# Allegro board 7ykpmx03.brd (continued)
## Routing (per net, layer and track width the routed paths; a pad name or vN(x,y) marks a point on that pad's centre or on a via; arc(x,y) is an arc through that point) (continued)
GND_OSC1: length 2.5
  TOP w0.254: R45.1 R47.2 X_OSC1.3
GND_SIGNAL: length 331.3
  TOP w0.254: 170.56,302.29 C127.1 ; C127.1 170.13,302.72 ; C127.1 170.99,302.72 ; 168.86,302.72 C128.1 ; C128.1 169.29,302.29 ; C128.1 169.72,302.72 ; C125.1 170.56,306.04 ; C125.1 170.13,305.61 ; C125.1 170.99,305.61 ; 171.4,302.72 R184.1 ; R184.1 172.26,302.72 ; R184.1 171.83,302.29 ; C126.1 169.29,306.04 ; C126.1 168.86,305.61 ; C126.1 169.72,305.61 ; 171.4,305.61 R183.1 ; R183.1 171.83,306.04 ; R183.1 172.26,305.61
  TOP w0.381: P_OCPEDGE.A19 128.31,323.9 v1(128.11,323.7) ; P_OCPEDGE.A22 126.51,323.9 v1(126.31,323.7) ; P_OCPEDGE.A16 130.11,323.9 v1(129.91,323.7) ; v1(104.19,323.7) 104.39,323.9 P_OCPEDGE.A46 ; v1(124.51,323.7) 124.71,323.9 P_OCPEDGE.A25 ; v1(115.1,323.7) 115.3,323.9 P_OCPEDGE.A35 ; v1(131.71,323.7) 131.91,323.9 P_OCPEDGE.A13 ; P_OCPEDGE.A29 118.9,323.9 v1(118.7,323.7) ; P_OCPEDGE.A41 111.7,323.9 v1(111.5,323.7) ; P_OCPEDGE.A61 95.39,323.9 v1(95.19,323.7) ; P_OCPEDGE.A67 91.79,323.9 v1(91.59,323.7) ; P_OCPEDGE.A28 122.91,323.9 v1(122.71,323.7) ; v1(105.99,323.7) 106.19,323.9 P_OCPEDGE.A43 ; P_OCPEDGE.A38 113.5,323.9 v1(113.3,323.7) ; P_OCPEDGE.A49 102.59,323.9 v1(102.39,323.7) ; v1(93.39,323.7) 93.59,323.9 P_OCPEDGE.A64 ; P_OCPEDGE.OCP_A13 144.11,323.9 v1(143.9,323.7) ; P_OCPEDGE.A55 98.99,323.9 v1(98.79,323.7) ; P_OCPEDGE.A52 100.79,323.9 v1(100.59,323.7) ; v1(96.99,323.7) 97.19,323.9 P_OCPEDGE.A58 ; P_OCPEDGE.A32 117.1,323.9 v1(116.9,323.7) ; v1(145.7,323.7) 145.91,323.9 P_OCPEDGE.OCP_A10
  GND w0.254: P_CAL_CPU_OCP_0_P.2 178.99,299.09 ; P_CAL_CPU_OCP_0_P.2 178.99,300.21 ; P_CAL_CPU_OCP_0_P.2 177.86,300.21 ; P_CAL_CPU_OCP_0_N.5 178.99,308.12 ; P_CAL_CPU_OCP_0_N.5 177.86,308.12 ; P_CAL_CPU_OCP_0_N.5 178.99,309.24 ; 71.93,314.45 J_S2D_BOT.1 ; J_S2D_BOT.1 72.85,314.45 ; J_S2D_BOT.1 72.39,313.23 ; J_S2D_BOT.1 72.39,315.67 ; P_CAL_CPU_OCP_0_P.3 178.99,295.74 ; P_CAL_CPU_OCP_0_P.3 177.86,295.74 ; P_CAL_CPU_OCP_0_P.3 177.86,296.86 ; P_CAL_CPU_OCP_0_P.3 178.99,296.86 ; P_CAL_CPU_OCP_0_N.3 174.69,311.47 ; P_CAL_CPU_OCP_0_N.3 173.56,311.47 ; P_CAL_CPU_OCP_0_N.3 174.69,312.59 ; P_CAL_CPU_OCP_0_N.3 173.56,312.59 ; P_CAL_CPU_OCP_0_P.4 174.69,296.86 ; P_CAL_CPU_OCP_0_P.4 173.56,296.86 ; P_CAL_CPU_OCP_0_P.4 173.56,295.74 ; P_CAL_CPU_OCP_0_P.4 174.69,295.74 ; J_S2D_TOP.1 72.85,294 ; J_S2D_TOP.1 72.39,295.22 ; J_S2D_TOP.1 72.39,292.79 ; J_S2D_TOP.1 71.93,294 ; 177.86,311.47 P_CAL_CPU_OCP_0_N.4 ; P_CAL_CPU_OCP_0_N.4 178.99,312.59 ; P_CAL_CPU_OCP_0_N.4 177.86,312.59 ; P_CAL_CPU_OCP_0_N.4 178.99,311.47 ; P_CAL_CPU_OCP_0_P.5 174.69,300.21 ; P_CAL_CPU_OCP_0_P.5 173.56,300.21 ; P_CAL_CPU_OCP_0_P.5 173.56,299.09 ; P_CAL_CPU_OCP_0_N.2 174.69,308.12 ; P_CAL_CPU_OCP_0_N.2 173.56,308.12 ; P_CAL_CPU_OCP_0_N.2 173.56,309.24
  VCC w0.254: P_CAL_CPU_OCP_0_N.5 178.99,308.12 ; P_CAL_CPU_OCP_0_N.5 177.86,308.12 ; P_CAL_CPU_OCP_0_N.5 178.99,309.24 ; 173.56,300.21 P_CAL_CPU_OCP_0_P.5 ; P_CAL_CPU_OCP_0_P.5 174.69,300.21 ; P_CAL_CPU_OCP_0_P.5 173.56,299.09 ; P_CAL_CPU_OCP_0_P.2 178.99,299.09 ; P_CAL_CPU_OCP_0_P.2 177.86,300.21 ; P_CAL_CPU_OCP_0_P.2 178.99,300.21 ; 72.39,313.23 J_S2D_BOT.1 ; J_S2D_BOT.1 72.85,314.45 ; J_S2D_BOT.1 71.93,314.45 ; J_S2D_BOT.1 72.39,315.67 ; P_CAL_CPU_OCP_0_N.3 174.69,311.47 ; P_CAL_CPU_OCP_0_N.3 173.56,312.59 ; P_CAL_CPU_OCP_0_N.3 174.69,312.59 ; P_CAL_CPU_OCP_0_N.3 173.56,311.47 ; 173.56,296.86 P_CAL_CPU_OCP_0_P.4 ; P_CAL_CPU_OCP_0_P.4 173.56,295.74 ; P_CAL_CPU_OCP_0_P.4 174.69,295.74 ; P_CAL_CPU_OCP_0_P.4 174.69,296.86 ; 177.86,295.74 P_CAL_CPU_OCP_0_P.3 ; P_CAL_CPU_OCP_0_P.3 178.99,295.74 ; P_CAL_CPU_OCP_0_P.3 177.86,296.86 ; P_CAL_CPU_OCP_0_P.3 178.99,296.86 ; P_CAL_CPU_OCP_0_N.4 178.99,311.47 ; P_CAL_CPU_OCP_0_N.4 177.86,312.59 ; P_CAL_CPU_OCP_0_N.4 178.99,312.59 ; P_CAL_CPU_OCP_0_N.4 177.86,311.47 ; 173.56,308.12 P_CAL_CPU_OCP_0_N.2 ; P_CAL_CPU_OCP_0_N.2 173.56,309.24 ; P_CAL_CPU_OCP_0_N.2 174.69,308.12 ; J_S2D_TOP.1 72.39,295.22 ; J_S2D_TOP.1 71.93,294 ; J_S2D_TOP.1 72.85,294 ; J_S2D_TOP.1 72.39,292.79
  GD2 w0.254: 177.86,309.24 P_CAL_CPU_OCP_0_N.5 ; P_CAL_CPU_OCP_0_N.5 178.99,308.12 ; P_CAL_CPU_OCP_0_N.5 178.99,309.24 ; P_CAL_CPU_OCP_0_N.5 177.86,308.12 ; P_CAL_CPU_OCP_0_N.4 178.99,312.59 ; P_CAL_CPU_OCP_0_N.4 177.86,312.59 ; P_CAL_CPU_OCP_0_N.4 178.99,311.47 ; P_CAL_CPU_OCP_0_N.4 177.86,311.47 ; P_CAL_CPU_OCP_0_N.2 174.69,309.24 ; P_CAL_CPU_OCP_0_N.2 174.69,308.12 ; P_CAL_CPU_OCP_0_N.2 173.56,308.12 ; P_CAL_CPU_OCP_0_N.2 173.56,309.24 ; P_CAL_CPU_OCP_0_N.3 174.69,311.47 ; P_CAL_CPU_OCP_0_N.3 174.69,312.59 ; P_CAL_CPU_OCP_0_N.3 173.56,312.59 ; P_CAL_CPU_OCP_0_N.3 173.56,311.47 ; 173.56,300.21 P_CAL_CPU_OCP_0_P.5 ; P_CAL_CPU_OCP_0_P.5 173.56,299.09 ; P_CAL_CPU_OCP_0_P.5 174.69,299.09 ; P_CAL_CPU_OCP_0_P.5 174.69,300.21 ; J_S2D_BOT.1 72.39,315.67 ; J_S2D_BOT.1 72.85,314.45 ; J_S2D_BOT.1 72.39,313.23 ; J_S2D_BOT.1 71.93,314.45 ; 177.86,296.86 P_CAL_CPU_OCP_0_P.3 ; P_CAL_CPU_OCP_0_P.3 178.99,296.86 ; P_CAL_CPU_OCP_0_P.3 178.99,295.74 ; P_CAL_CPU_OCP_0_P.3 177.86,295.74 ; P_CAL_CPU_OCP_0_P.4 174.69,295.74 ; P_CAL_CPU_OCP_0_P.4 173.56,296.86 ; P_CAL_CPU_OCP_0_P.4 173.56,295.74 ; P_CAL_CPU_OCP_0_P.4 174.69,296.86 ; J_S2D_TOP.1 72.85,294 ; J_S2D_TOP.1 71.93,294 ; J_S2D_TOP.1 72.39,295.22 ; J_S2D_TOP.1 72.39,292.79 ; P_CAL_CPU_OCP_0_P.2 178.99,300.21 ; P_CAL_CPU_OCP_0_P.2 178.99,299.09 ; P_CAL_CPU_OCP_0_P.2 177.86,299.09 ; P_CAL_CPU_OCP_0_P.2 177.86,300.21
  GD3 w0.254: P_CAL_CPU_OCP_0_P.4 174.69,295.74 ; P_CAL_CPU_OCP_0_P.4 173.56,296.86 ; P_CAL_CPU_OCP_0_P.4 174.69,296.86 ; P_CAL_CPU_OCP_0_P.4 173.56,295.74 ; 177.86,300.21 P_CAL_CPU_OCP_0_P.2 ; P_CAL_CPU_OCP_0_P.2 177.86,299.09 ; P_CAL_CPU_OCP_0_P.2 178.99,299.09 ; P_CAL_CPU_OCP_0_P.2 178.99,300.21 ; P_CAL_CPU_OCP_0_P.5 174.69,300.21 ; P_CAL_CPU_OCP_0_P.5 174.69,299.09 ; P_CAL_CPU_OCP_0_P.5 173.56,300.21 ; P_CAL_CPU_OCP_0_P.5 173.56,299.09 ; 173.56,308.12 P_CAL_CPU_OCP_0_N.2 ; P_CAL_CPU_OCP_0_N.2 173.56,309.24 ; P_CAL_CPU_OCP_0_N.2 174.69,309.24 ; P_CAL_CPU_OCP_0_N.2 174.69,308.12 ; 177.86,312.59 P_CAL_CPU_OCP_0_N.4 ; P_CAL_CPU_OCP_0_N.4 178.99,312.59 ; P_CAL_CPU_OCP_0_N.4 177.86,311.47 ; P_CAL_CPU_OCP_0_N.4 178.99,311.47 ; P_CAL_CPU_OCP_0_N.3 174.69,312.59 ; P_CAL_CPU_OCP_0_N.3 173.56,312.59 ; P_CAL_CPU_OCP_0_N.3 173.56,311.47 ; P_CAL_CPU_OCP_0_N.3 174.69,311.47 ; P_CAL_CPU_OCP_0_N.5 178.99,308.12 ; P_CAL_CPU_OCP_0_N.5 177.86,309.24 ; P_CAL_CPU_OCP_0_N.5 177.86,308.12 ; P_CAL_CPU_OCP_0_N.5 178.99,309.24 ; J_S2D_TOP.1 72.85,294 ; J_S2D_TOP.1 71.93,294 ; J_S2D_TOP.1 72.39,292.79 ; J_S2D_TOP.1 72.39,295.22 ; P_CAL_CPU_OCP_0_P.3 178.99,295.74 ; P_CAL_CPU_OCP_0_P.3 178.99,296.86 ; P_CAL_CPU_OCP_0_P.3 177.86,296.86 ; P_CAL_CPU_OCP_0_P.3 177.86,295.74 ; 71.93,314.45 J_S2D_BOT.1 ; J_S2D_BOT.1 72.39,315.67 ; J_S2D_BOT.1 72.85,314.45 ; J_S2D_BOT.1 72.39,313.23
  BOTTOM w0.381: P_OCPEDGE.OCP_A13 144.11,323.9 v1(143.9,323.7) ; P_OCPEDGE.A58 97.19,323.9 v1(96.99,323.7) ; v1(113.3,323.7) 113.5,323.9 P_OCPEDGE.A38 ; v1(104.19,323.7) 104.39,323.9 P_OCPEDGE.A46 ; P_OCPEDGE.A22 126.51,323.9 v1(126.31,323.7) ; P_OCPEDGE.A28 122.91,323.9 v1(122.71,323.7) ; P_OCPEDGE.OCP_A6 148.31,323.9 v1(148.1,323.7) ; P_OCPEDGE.A61 95.39,323.9 v1(95.19,323.7) ; v1(118.7,323.7) 118.9,323.9 P_OCPEDGE.A29 ; P_OCPEDGE.A19 128.31,323.9 v1(128.11,323.7) ; v1(93.39,323.7) 93.59,323.9 P_OCPEDGE.A64 ; v1(115.1,323.7) 115.3,323.9 P_OCPEDGE.A35 ; v1(116.9,323.7) 117.1,323.9 P_OCPEDGE.A32 ; v1(129.91,323.7) 130.11,323.9 P_OCPEDGE.A16 ; P_OCPEDGE.A67 91.79,323.9 v1(91.59,323.7) ; P_OCPEDGE.A43 106.19,323.9 v1(105.99,323.7) ; P_OCPEDGE.A49 102.59,323.9 v1(102.39,323.7) ; v1(111.5,323.7) 111.7,323.9 P_OCPEDGE.A41 ; P_OCPEDGE.A52 100.79,323.9 v1(100.59,323.7) ; v1(131.71,323.7) 131.91,323.9 P_OCPEDGE.A13 ; P_OCPEDGE.OCP_A10 145.91,323.9 v1(145.7,323.7) ; v1(98.79,323.7) 98.99,323.9 P_OCPEDGE.A55 ; v1(124.51,323.7) 124.71,323.9 P_OCPEDGE.A25
  vias: v1(136.02,323.7) v1(136.91,323.7) v1(137.8,323.7) v1(138.68,323.7) v1(169.29,306.45) v1(169.29,301.88) v1(170.56,306.45) v1(170.56,301.88) v1(171.83,306.45) v1(171.83,301.88) v2(175.53,309.88) v2(175.53,298.45) v2(175.63,310.25) v2(175.63,309.51) v2(175.63,298.82) v2(175.63,298.08) v2(175.9,310.53) v2(175.9,297.8) v2(176.28,310.63) v2(176.28,297.7) v2(176.65,310.53) v2(176.65,297.8) v2(176.92,310.25) v2(176.92,309.51) v2(176.92,298.82) v2(176.92,298.08) v2(177.03,309.88) v2(177.03,298.45)
VCC_OSC1: length 4.2
  TOP w0.254: C23.1 111.47,251.78 ; C23.1 111.14,251.46 ; C23.1 111.8,251.46 ; 112.43,254.84 R37.1 ; R37.1 112.86,254.41 ; R37.1 113.3,254.84 ; R35.1 112.81,251.46 ; R35.1 112.48,251.78 ; R35.1 112.16,251.46 ; R36.1 110.78,251.46 ; R36.1 110.45,251.78 ; R36.1 110.12,251.46
317_ADJ: length 4.1
  TOP w0.102: 116.55,256.83 116.55,258.27 R94.2 115.58,258.78 115.44,258.91 115.44,259.46 115.27,259.64 R96.1
337_ADJ: length 3.4
  TOP w0.102: R100.2 R99.1 163.83,238.38 163.82,238.37 U10.1
555_DISCHARGE: length 0.9
  TOP w0.254: 13.77,219.63 R24.1 14.2,219.2
555_OUT: length 3.1
  TOP w0.102: 22.74,220.34 22.74,220.72 22.56,220.9 R27.1 22.1,221.23 21.72,220.85 20.61,220.85
555_OUT_JP: length 11.4
  TOP w0.102: R27.2 v1(24.26,221.23)
  BOTTOM w0.102: v1(24.26,221.23) 24.64,221.62 27.56,221.62 28.32,220.85 32.51,220.85 P3.1
555_RST_N: length 3.6
  TOP w0.102: C11.1 22.28,223.22 22.56,222.94 R26.2 22.1,222.38 21.84,222.12 20.61,222.12
555_TRI: length 26
  TOP w0.102: R19.2 17.02,238.76 16.26,238 16.26,225.55 18.8,223.01 18.8,220.09 19.3,219.58 22.74,219.58
ATX_PS_ON_N: length 78
  TOP w0.102: SW_PWR.5 212.34,253.11 212.34,250.32 211.51,249.48 DS2.4
  BOTTOM w0.102: P_ATX.16 161.67,252.61 175.39,252.61 178.56,255.78 178.56,257.3 179.2,257.94 181.23,257.94 182.25,256.92 182.25,249.43 183.64,248.03 207.52,248.03 210.44,250.95 210.44,253.17 SW_PWR.5
ATX_PWR_OK: length 170.4
  TOP w0.102: R102.2 22.56,245.19 v1(22.48,245.11)
  BOTTOM w0.102: P_ATX.8 168.05,264.54 73.79,264.54 63.25,254 28.58,254 24.64,250.06 22.23,250.06 21.84,249.68 21.84,248.41 22.48,247.78 v1(22.48,245.11)
ATX_PWR_OK_33: length 3
  TOP w0.102: R102.1 R103.2 24.13,247.65 24.2,247.72 U11.3
AUX_PWR_EN: length 280.5
  TOP w0.102: v1(91.82,88.39) 91.86,88.35 P_OCP.B12 ; v1(21.59,245.11) 21.21,245.49 21.21,248.03 21.72,248.54 26.92,248.54 27.21,248.25 U11.2 28.01,247.72 28.07,247.78 R104.2 28.78,249.61 28.27,250.12 U12.3
  BOTTOM w0.102: v1(91.82,88.39) 91.82,85.34 92.33,84.84 92.33,84.07 90.96,82.7 87.1,82.7 86.61,83.19 82.64,83.19 74.39,74.93 47.5,74.93 45.09,77.34 35.05,77.34 27.81,84.58 27.81,106.3 49.15,127.64 49.15,199.64 33.08,215.71 27.11,215.71 22.99,219.84 22.99,224.03 19.3,227.71 19.3,242.32 21.59,244.6 v1(21.59,245.11)
BIF0_N: length 70.4
  TOP w0.102: R14.2 38.35,88.9 38.53,88.72 R12.2 38.53,87.3 38.28,87.05 37.13,87.05 36.83,86.74 36.83,84.2 35.81,83.19 35.81,81.66 v1(36.2,81.28) ; v1(85.72,85.09) 86.11,85.47 88.52,85.47 88.86,85.81 P_OCP.B7
  BOTTOM w0.102: v1(36.2,81.28) 36.2,80.9 35.56,80.26 35.56,79.25 36.07,78.74 47.37,78.74 48.77,77.34 68.96,77.34 70.61,78.99 77.48,78.99 83.58,85.09 v1(85.72,85.09)
BIF1_N: length 70.6
  TOP w0.102: R6.2 36.32,88.78 36.5,88.6 R13.2 36.5,87.17 36.2,86.87 36.2,84.46 35.18,83.45 v1(35.18,81.28) ; v1(87,84.71) 87.5,85.22 89.03,85.22 89.46,85.65 P_OCP.B8
  BOTTOM w0.102: v1(87,84.71) 86.11,84.71 85.98,84.58 83.39,84.58 77.42,78.61 71.25,78.61 69.22,76.58 47.88,76.58 46.1,78.36 35.91,78.36 35.18,79.09 v1(35.18,81.28)
BIF2_N: length 73.3
  TOP w0.102: R7.2 34.29,88.78 34.47,88.6 R5.2 34.47,87.71 35.56,86.61 35.56,84.73 34.54,83.71 34.54,81.66 v1(34.16,81.28) ; v1(88.01,84.71) 88.9,84.71 90.06,85.87 P_OCP.B9
  BOTTOM w0.102: v1(34.16,81.28) 34.16,80.9 34.8,80.26 34.8,78.93 35.75,77.98 44.96,77.98 47.62,75.31 74.45,75.31 83.34,84.2 87.25,84.2 87.76,84.71 v1(88.01,84.71)
BTN_NC: length 16.9
  TOP w0.102: U1.1 21.03,236.24 20.83,236.44 v1(20.83,236.86) ; SW1.1 20.45,228.73 21.21,227.97 v1(21.21,227.46) 21.46,227.21 R31.1 R20.1
  BOTTOM w0.102: v1(21.21,227.46) 19.94,228.73 19.94,235.97 v1(20.83,236.86)
BTN_NO: length 36.3
  TOP w0.102: U6.2 21.21,229.24 20.7,229.74 20.7,231.14 21.59,232.03 21.59,232.79 20.83,233.55 19.5,233.55 19.14,233.91 SW1.3 19.14,238.21 19.3,238.38 19.3,238.76 R19.1 19.3,239.15 19.18,239.27 18.69,239.27 18.62,239.34 R28.1 v1(18.62,240.74) ; DS1.4 v1(20.7,259.64)
  BOTTOM w0.102: v1(18.62,240.74) 18.62,257.56 v1(20.7,259.64)
BUS_SEL: length 230
  TOP w0.102: R30.1 24.77,220.98 24.13,220.34 R29.1 ; R30.1 25.35,221.54 25.2,221.69 C15.1 ; R30.1 25.35,220.78 26.54,219.58 P4.1 30.73,220.98 30.73,222.5 27.81,225.43 21.34,225.43 20.96,225.8 R31.2 ; U8.10 105.56,240.01 105.28,239.74 105.28,239.4 v1(104.77,238.89) ; Q2.1 189.61,229.55 v1(189.61,229.56) ; v1(52.7,217.17) v1(29.84,217.17)
  BOTTOM w0.102: v1(189.61,229.56) 188.02,227.97 152.27,227.97 141.35,238.89 v1(104.77,238.89) 106.05,237.62 106.05,231.39 104.9,230.25 81.91,230.25 78.99,227.33 78.99,216.28 80.01,215.27 80.01,210.06 79.12,209.17 65.02,209.17 64.01,210.19 56.9,210.19 55.24,211.84 55.24,214.63 v1(52.7,217.17) ; v1(29.84,217.17) 29.84,219.08 P4.1
CLK_BASE_TO_DEVICE_DN: length 103.1
  TOP w0.127: R111.1 62.51,206.76 ; 62.51,206.76 62.38,206.63 62.38,204.59 62.51,204.47 ; 62.51,206.76 62.38,206.89 62.38,210.54 61.34,211.58 61.34,212.52 61.31,212.7 61.56,214.14 61.12,216.64 61.56,219.14 61.12,221.64 61.34,222.89 61.34,223.75 v1(61.61,224.03) ; v1(66.39,222.76) 66.67,222.48 66.67,221.48 66.62,221.43 U19.7 ; 62.51,202.56 62.38,202.43 62.38,200.78 62.51,200.66 ; 62.51,202.56 62.38,202.69 62.38,204.34 62.51,204.47 ; 62.51,202.56 R115.1 ; 69.73,244.7 69.61,244.82 69.61,245.48 69.22,245.87 67.26,245.87 65.48,244.09 65.48,243.46 65.7,242.21 65.37,240.32 65.48,239.67 65.48,239.14 59.89,233.55 59.89,232.83 60.11,231.58 59.8,229.81 59.89,229.29 59.89,228.85 55.7,224.66 55.7,223.99 55.92,222.74 55.48,220.24 55.92,217.73 55.48,215.23 55.92,212.73 55.48,210.23 55.92,207.73 55.48,205.23 55.73,203.8 55.7,203.63 55.7,202.46 59.72,198.45 61.98,198.45 62.38,198.86 62.38,200.53 62.51,200.66 ; 69.73,244.7 69.61,244.57 69.61,244.08 69.85,243.84 73.16,243.84 R55.2 ; 69.73,244.7 SW_BUF_SRC.5 ; 62.51,204.47 R113.1 ; 62.51,200.66 R117.1
  BOTTOM w0.127: v1(61.61,224.03) 61.34,224.3 61.34,224.54 61.72,224.92 66.04,224.92 66.67,224.29 66.67,223.03 v1(66.39,222.76)
CLK_BASE_TO_DEVICE_DP: length 102.6
  TOP w0.127: 61.95,204.47 62.08,204.59 62.08,206.63 61.95,206.76 ; 61.95,204.47 62.08,204.34 62.08,202.69 61.95,202.56 ; 61.95,204.47 R112.1 ; 61.95,206.76 62.08,206.89 62.08,210.41 61.04,211.46 61.04,212.5 61,212.7 61.25,214.14 60.81,216.64 61.25,219.14 60.81,221.64 61.04,222.92 61.04,223.75 v1(60.76,224.03) ; 61.95,206.76 R110.1 ; 61.95,202.56 62.08,202.43 62.08,200.78 61.95,200.66 ; 61.95,202.56 R114.1 ; v1(67.24,222.76) 66.97,222.48 66.97,221.5 67.02,221.45 U19.6 ; R116.1 61.95,200.66 ; 61.95,200.66 62.08,200.53 62.08,198.98 61.85,198.76 59.84,198.76 56.01,202.59 56.01,203.61 56.04,203.8 55.79,205.23 56.23,207.73 55.79,210.23 56.23,212.73 55.79,215.23 56.23,217.73 55.79,220.24 56.23,222.74 56.01,224.01 56.01,224.54 60.2,228.73 60.2,229.31 60.11,229.81 60.42,231.58 60.2,232.85 60.2,233.43 65.79,239.01 65.79,239.7 65.68,240.32 66.01,242.21 65.79,243.49 65.79,243.97 67.39,245.57 69.09,245.57 69.3,245.36 69.3,244.82 69.17,244.7 ; SW_BUF_SRC.2 69.17,244.7 ; 69.17,244.7 69.3,244.57 69.3,243.96 69.72,243.54 73.08,243.54 R56.2
  BOTTOM w0.127: v1(60.76,224.03) 61.04,224.3 61.04,224.66 61.6,225.22 66.17,225.22 66.97,224.42 66.97,223.03 v1(67.24,222.76)
CLK_BASE_TO_DEVICE_R_DN: length 21.7
  TOP w0.127: P_NOISEINJ_N.1 84.35,234.32 84.23,234.44 84.23,235.38 84.32,235.92 84.01,237.69 84.45,240.19 84.23,241.47 84.23,242.29 82.72,243.8 82.17,243.8 80.93,244.02 78.44,243.58 75.94,244.02 74.69,243.8 73.95,243.8 R55.1
CLK_BASE_TO_DEVICE_R_DP: length 21.2
  TOP w0.127: R56.1 73.95,243.5 74.71,243.5 75.94,243.71 78.44,243.27 80.93,243.71 82.14,243.5 82.59,243.5 83.92,242.16 83.92,241.44 84.14,240.19 83.7,237.69 84.01,235.92 83.92,235.41 83.92,234.44 83.79,234.32 P_NOISEINJ_P.1
CLK_EXTERNAL_DN: length 27.4
  TOP w0.127: SW_BUF_SRC.6 69.73,246.7 69.61,246.82 69.61,247 70.25,247.65 71.37,247.65 71.93,247.09 72.24,247.09 73.44,246.88 75.87,247.31 78.37,246.87 80.88,247.31 82.1,247.09 82.65,247.09 83.6,248.04 83.6,249.72 v1(83.82,249.94) 83.59,250.16 83.59,250.52 C25.2 83.59,251.38 83.59,251.89 83.64,252.16 83.37,253.69 83.59,254.94 83.59,255.27 83.72,255.4 P_EXT_CLK_N.1
  BOTTOM w0.127: v1(83.82,249.94) 83.6,249.72 83.6,249.32 R53.1
CLK_EXTERNAL_DP: length 27.4
  TOP w0.127: SW_BUF_SRC.3 69.17,246.7 69.3,246.82 69.3,247.13 70.13,247.95 71.5,247.95 72.06,247.4 72.26,247.4 73.44,247.19 75.87,247.62 78.37,247.18 80.88,247.62 82.13,247.4 82.52,247.4 83.3,248.17 83.3,249.69 v1(83.06,249.94) 83.29,250.16 83.29,250.52 C26.2 83.29,251.38 83.29,251.92 83.33,252.16 83.06,253.69 83.29,254.96 83.29,255.22 83.11,255.4 P_EXT_CLK_P.1
  BOTTOM w0.127: R54.1 83.3,249.35 83.3,249.69 v1(83.06,249.94)
CLK_NCSI: length 50.5
  TOP w0.102: v1(77.09,89.53) 77.6,89.03 80.01,89.03 80.87,89.88 P_OCP.OCP_A14
  BOTTOM w0.102: TP18.TEST 42.8,99.06 47.88,93.98 71.12,93.98 73.15,91.95 76.07,91.95 77.09,90.93 v1(77.09,89.53)
CLK_OSC1_TO_TRIGGER_DN: length 42.7
  TOP w0.127: X_OSC1.5 108.29,252.41 107.85,251.97 107.28,251.97 107.11,251.8 107.11,251.21 107.21,251.1 ; 107.21,251.1 R48.2 ; 107.21,251.1 107.1,250.99 107.1,250.37 R38.1 107.1,249.96 107.1,249.61 107.28,249.43 v1(107.3,249.43) 107.09,249.21 107.09,241.6 107.13,241.56 U8.6
  BOTTOM w0.127: R53.2 83.59,248.5 83.59,248.06 84.25,247.4 84.81,247.4 86.04,247.18 88.54,247.62 91.04,247.18 93.54,247.62 96.04,247.18 98.05,247.53 98.83,247.4 99.14,247.4 104.01,252.27 105.66,252.27 107.1,250.84 107.1,249.63 v1(107.3,249.43)
CLK_OSC1_TO_TRIGGER_DP: length 42.7
  TOP w0.127: U8.7 106.73,241.56 106.78,241.6 106.78,249.21 v1(106.57,249.43) 106.79,249.66 106.79,249.96 R39.1 106.79,250.37 106.79,251 106.69,251.1 ; X_OSC1.4 105.75,252.22 106.01,251.97 106.64,251.97 106.81,251.8 106.81,251.22 106.69,251.1 ; 106.69,251.1 R49.2
  BOTTOM w0.127: R54.2 83.29,248.5 83.29,247.93 84.12,247.09 84.79,247.09 86.04,246.87 88.54,247.31 91.04,246.87 93.54,247.31 96.04,246.87 98.05,247.22 98.81,247.09 99.26,247.09 104.14,251.97 105.54,251.97 106.79,250.71 106.79,249.66 v1(106.57,249.43)
CLK_OSC2_TO_DEVICE_DN: length 32.2
  TOP w0.127: R44.1 v1(57.45,241.94) 57.32,241.81 U18.13
  BOTTOM w0.127: v1(57.45,241.94) 57.22,241.71 56.95,241.71 56.82,241.83 56.82,242.75 57.61,243.54 59.94,243.54 60.4,243.08 60.4,239.01 62.74,236.68 70.81,236.68 72.06,237.92 72.06,238.55 72.27,238.76 72.27,238.96 72.06,239.18 72.06,239.62 71.35,240.34 71.35,240.64 71.2,240.78 70.9,240.78 70.59,241.09 70.59,241.39 70.45,241.54 70.15,241.54 69.61,242.08 69.61,242.57 69.73,242.7 SW_BUF_SRC.4
CLK_OSC2_TO_DEVICE_DP: length 32.2
  TOP w0.127: U18.12 57.21,241.41 v1(57.45,241.17) R43.1
  BOTTOM w0.127: SW_BUF_SRC.1 69.17,242.7 69.3,242.57 69.3,241.95 70.04,241.21 71.75,239.5 71.75,238.05 70.69,236.98 62.86,236.98 60.71,239.14 60.71,243.21 60.07,243.84 57.48,243.84 56.52,242.87 56.52,241.71 56.82,241.4 57.22,241.4 v1(57.45,241.17)
CLK_TRIG_SIGNAL_C_DN: length 1.4
  TOP w0.127: R34.1 107.19,236.91 107.06,237.03 107.06,237.67 C18.1
CLK_TRIG_SIGNAL_C_DP: length 1.4
  TOP w0.127: R32.1 106.6,236.91 106.76,237.06 106.76,237.7 C17.1
CLK_TRIG_SIGNAL_DN: length 1.5
  TOP w0.127: U8.2 107.13,239.26 107.09,239.21 107.09,238.55 C18.2
CLK_TRIG_SIGNAL_DP: length 1.6
  TOP w0.127: U8.1 106.73,239.29 106.78,239.24 106.78,238.58 C17.2
CLK_TRIG_SIGNAL_R_DN: length 4.3
  TOP w0.127: P_CMTS_N.1 107.21,234.32 107.09,234.44 107.09,235.64 R34.2
CLK_TRIG_SIGNAL_R_DP: length 4.3
  TOP w0.127: R32.2 106.78,235.61 106.78,234.44 106.65,234.32 P_CMTS_P.1
CLKBUF_EN: length 31.1
  TOP w0.102: U15.3 v1(40.44,248.48) 39.5,249.43 39.5,251.84 37.85,253.49 32.89,253.49 32.53,253.13 U14.4 ; v1(50.88,246.13) U21.2 52.32,246.13 52.58,245.87 52.58,244.73 52.93,244.37 U18.1
  BOTTOM w0.102: v1(40.44,248.48) 43.31,245.62 49.4,245.62 49.91,246.13 v1(50.88,246.13)
CLKBUF_EN_DLY: length 4.4
  TOP w0.102: R118.1 46.99,249.98 46.56,249.56 45.97,249.56 45.67,249.25 R108.2 45.09,248.54 45.03,248.48 44.1,248.48
CLKBUF_EN_N: length 66
  TOP w0.102: v1(74.2,218.34) U20.5 74.2,213.39 v1(73.55,212.74) U20.9 ; U21.4 v1(54.27,245.48) ; U20.12 v1(75.5,210.26) ; U20.2 v1(76.15,215.86)
  BOTTOM w0.102: v1(75.5,210.26) 75.5,211.39 74.68,212.22 74.08,212.22 v1(73.55,212.74) ; v1(74.2,218.34) 75.44,217.11 75.44,216.15 75.74,215.86 v1(76.15,215.86) 76.15,223.69 73.41,226.44 73.41,233.17 71.37,235.2 61.59,235.2 57.91,238.89 54.61,238.89 53.09,240.41 53.09,242.57 53.85,243.33 54.74,243.33 55.01,243.6 55.01,244.74 v1(54.27,245.48)
CLKBUF_OE0_N: length 19.5
  TOP w0.102: v1(70.48,216.92) 70.48,217.81 70.16,218.13 U19.22 ; SW_OE0.2 82.51,221.11 78.11,221.11 75.5,218.51 v1(75.5,218.34) U20.3
  BOTTOM w0.102: v1(75.5,218.34) 74.65,219.2 72.01,219.2 70.48,217.68 v1(70.48,216.92)
CLKBUF_OE0_OFF: length 3.4
  TOP w0.102: SW_OE0.1 83.98,222.5 R86.1
CLKBUF_OE0_ON: length 3.3
  TOP w0.102: SW_OE0.3 83.79,217.82 R90.2
CLKBUF_OE0_OVERRIDE: length 7.9
  TOP w0.102: U20.1 v1(76.8,218.34) 78.52,220.06 SW_OE0.5
  BOTTOM w0.102: v1(76.8,218.34) 76.71,218.25 R210.1
CLKBUF_OE1_N: length 40.4
  TOP w0.102: SW_OE1.2 91.31,208.49 91.31,210.44 88.27,213.49 80.14,213.49 79.63,214 78.36,214 v1(77.72,213.36) ; U20.6 v1(73.55,215.86) ; v1(65.02,217.68) 65.48,218.13 U19.14
  BOTTOM w0.102: v1(77.72,213.36) 76.71,213.36 74.93,215.14 74.27,215.14 v1(73.55,215.86) 71.44,213.74 70.1,213.74 68.96,212.6 66.67,212.6 65.79,213.49 65.79,216.28 65.02,217.04 v1(65.02,217.68)
CLKBUF_OE1_OFF: length 3.6
  TOP w0.102: R87.1 93.51,210.43 SW_OE1.1
CLKBUF_OE1_ON: length 3.3
  TOP w0.102: R91.2 92.68,205.12 SW_OE1.3
CLKBUF_OE1_OVERRIDE: length 26.4
  TOP w0.102: SW_OE1.5 89.31,207.36 88.9,207.77 88.9,211.96 87.88,212.98 85.85,212.98 83.95,211.07 81.41,211.07 v1(79.12,213.36) ; U20.4 v1(74.85,215.86)
  BOTTOM w0.102: v1(79.12,213.36) 79.12,214 78.23,214.88 75.83,214.88 v1(74.85,215.86) 74.09,216.62 R213.2
CLKBUF_OE2_N: length 24
  TOP w0.102: U20.8 v1(72.9,210.26) 72.9,209.8 76.2,206.5 82.69,206.5 SW_OE2.2 ; v1(70.87,210.31) 70.87,215.27 69.02,217.11 U19.21
  BOTTOM w0.102: v1(72.9,210.26) 70.92,210.26 v1(70.87,210.31)
CLKBUF_OE2_OFF: length 3.6
  TOP w0.102: R88.1 84.62,210.43 SW_OE2.1
CLKBUF_OE2_ON: length 3.3
  TOP w0.102: SW_OE2.3 83.79,205.12 R92.2
CLKBUF_OE2_OVERRIDE: length 11.1
  TOP w0.102: U20.10 v1(74.2,210.26) 77.09,207.36 SW_OE2.5
  BOTTOM w0.102: v1(74.2,210.26) 74.22,210.27 R214.2
CLKBUF_OE3_N: length 44.3
  TOP w0.102: v1(64.14,219.84) 64.66,219.31 65.18,219.31 65.2,219.33 U19.11 ; SW_OE3.2 92.44,220.11 91.31,221.23 89.41,221.23 88.9,220.73 88.9,219.96 88.14,219.2 88.14,217.42 87.63,216.92 79.03,216.92 v1(74.85,212.74) U20.11
  BOTTOM w0.102: v1(74.85,212.74) 74.11,213.49 72.01,213.49 70.61,212.09 66.55,212.09 65.15,213.49 65.15,216.03 64.14,217.04 v1(64.14,219.84)
CLKBUF_OE3_OFF: length 3.4
  TOP w0.102: R89.1 92.87,222.5 SW_OE3.1
CLKBUF_OE3_ON: length 3.3
  TOP w0.102: SW_OE3.3 92.68,217.82 R93.2
CLKBUF_OE3_OVERRIDE: length 21.2
  TOP w0.102: SW_OE3.5 90.4,220.06 89.03,218.69 89.03,216.79 86.11,213.87 80.39,213.87 79.5,214.76 78.17,214.76 v1(76.15,212.74) U20.13
  BOTTOM w0.102: R215.2 76.2,212.7 v1(76.15,212.74)
MAIN_PWR_EN: length 287.1
  TOP w0.102: v1(73.66,84.45) 73.67,84.46 P_OCP.OCP_B2
  TOP w0.203: U19.9 65.27,220.13 64.64,220.76 64.64,221.11
  TOP w0.381: 64.64,221.11 64.64,222.38 64.31,222.71 64.31,222.96 62.99,224.28 v1(62.99,225.93) ; U12.2 24.19,250.12 24.13,250.06 R105.2 23.42,249.61 v1(22.99,249.17)
  TOP w0.508: U13.3 v1(31.24,248.23)
  BOTTOM w0.381: v1(31.24,248.23) 30.3,249.17 v1(22.99,249.17) ; v1(31.24,248.23) 31.31,248.23 32.51,249.43 35.18,249.43 50.16,234.44 58.8,234.44 60.2,233.05 60.2,228.73 v1(62.99,225.93) ; v1(31.24,248.23) 46.1,233.37 46.1,218.44 48.26,216.28 48.26,211.84 51.82,208.28 51.82,126.87 29.97,105.03 29.97,93.47 32.51,90.93 39.88,90.93 42.95,87.86 63.73,87.86 67.69,83.9 73.1,83.9 v1(73.66,84.45)
MAIN_PWR_EN_DLY: length 4.9
  TOP w0.305: R106.2 35.22,250.06 U14.1
  TOP w0.381: R106.2 36.65,249 35.89,248.23 U13.2
NCSI_ARBIN: length 46.3
  TOP w0.102: v1(74.8,93.34) 74.87,93.28 P_OCP.OCP_A4
  BOTTOM w0.102: v1(74.8,93.34) 74.8,93.6 71.5,96.9 60.41,96.9 56.6,100.71 34.92,100.71 TP12.TEST
NCSI_ARBOUT: length 44.5
  TOP w0.102: v1(75.44,92.71) 75.47,92.68 P_OCP.OCP_A5
  BOTTOM w0.102: TP15.TEST 56.68,101.35 60.62,97.41 71.75,97.41 75.44,93.73 v1(75.44,92.71)
NCSI_CRS_DV: length 51
  TOP w0.102: v1(80.87,87.63) P_OCP.OCP_B14
  BOTTOM w0.102: v1(80.87,87.63) 79.73,87.63 78.97,86.87 78.97,84.96 77.24,83.24 67.13,83.24 63.88,86.49 43.13,86.49 39.45,90.17 TP17.TEST
NCSI_RXD0: length 54.1
  TOP w0.102: v1(77.6,84.2) 77.6,84.71 77.87,84.98 P_OCP.OCP_B9
  BOTTOM w0.102: TP9.TEST 34.92,98.42 42.55,98.42 47.5,93.47 70.61,93.47 75.44,88.65 76.71,88.65 77.85,87.5 77.85,84.73 77.6,84.48 v1(77.6,84.2)
NCSI_RXD1: length 56.1
  TOP w0.102: P_OCP.OCP_B8 77.27,85.01 76.83,84.58 v1(76.83,84.2)
  BOTTOM w0.102: v1(76.83,84.2) 76.83,84.58 77.22,84.96 77.22,87.5 76.58,88.14 75.31,88.14 70.48,92.96 47.12,92.96 42.16,97.92 32.89,97.92 TP7.TEST
NCSI_TXD0: length 48.7
  TOP w0.102: P_OCP.OCP_A9 77.87,92.69 v1(77.85,92.71)
  BOTTOM w0.102: v1(77.85,92.71) 77.85,95.25 74.17,98.93 61.25,98.93 56.68,103.5 TP10.TEST
NCSI_TXD1: length 50.3
  TOP w0.102: P_OCP.OCP_A8 77.27,93.29 v1(77.22,93.34)
  BOTTOM w0.102: v1(77.22,93.34) 77.22,94.74 73.53,98.42 61.04,98.42 56.59,102.87 34.92,102.87 TP8.TEST
NCSI_TXEN: length 51.9
  TOP w0.102: v1(76.71,92.71) 76.67,92.67 P_OCP.OCP_A7
  BOTTOM w0.102: TP16.TEST 32.89,102.36 56.38,102.36 60.83,97.92 72.9,97.92 76.71,94.11 v1(76.71,92.71)
NIC_PWR_GOOD: length 224.1
  TOP w0.102: v1(73.02,85.09) 73.07,85.13 P_OCP.OCP_B1 ; v1(39,242.96) 39,251.7 38.61,252.09 37.08,252.09 36.65,251.66 R107.2 U14.2
  BOTTOM w0.102: v1(73.02,85.09) 69.34,85.09 65.28,89.15 44.83,89.15 41.73,92.25 33.58,92.25 31.12,94.72 31.12,104.01 52.96,125.86 52.96,214.38 49.25,218.08 49.25,220.22 49.53,220.5 49.53,228.98 47.31,231.2 47.31,234 39.56,241.74 39.56,242.4 v1(39,242.96)
PCIE_RST_BTN_N: length 385.8
  TOP w0.102: R15.1 R16.2 41.78,81.79 v1(41.15,81.15) R2.2 R8.2 ; v1(38.73,239.4) 39.5,239.4 46.35,246.25 46.35,247.02 46.86,247.52 48.39,247.52 49.76,248.89 49.76,253.52 49.02,254.25 44.58,254.25 42.73,252.41 U16.4 41.8,254.66 42.42,255.27 71.25,255.27 72.39,256.41 72.39,258.19 73.79,259.59 99.95,259.59 104.65,264.29 124.59,264.29 128.52,260.35 128.52,241.3 132.08,237.74 157.73,237.74 158.37,237.11 160.66,237.11 163.58,234.19 176.15,234.19 178.44,231.9 178.44,230.51 177.55,229.62 177.16,229.62 177.1,229.55 Q1.1
  BOTTOM w0.102: v1(38.73,239.4) 39.37,238.76 39.37,212.34 50.55,201.17 50.55,127.51 28.83,105.79 28.83,88.65 35.31,82.17 35.97,82.17 38,80.14 40.39,80.14 41.15,80.9 v1(41.15,81.15)
PCIE_RST_BTN_R: length 31.3
  TOP w0.102: C60.2 46.02,252.83 46.3,252.55 R185.1 U16.2 40.77,251.46 38.23,254 23.37,254 20.7,251.33 SW_RST.3
PE_CAL_CPU_OCP_0_DN: length 66.5
  TOP w0.127: P_OCPEDGE.B17 129.51,326.84 129.37,326.69 129.37,323.44 148.27,304.54 152.33,304.54 154.81,304.1 157.31,304.54 159.81,304.1 162.31,304.54 164.81,304.1 166.04,304.32 168.86,304.32 C126.2 169.72,304.32 170.13,304.32 C125.2 170.99,304.32 171.4,304.32 R183.2 172.26,304.32 173.11,304.32 173.23,304.44 173.23,304.47 173.36,304.6 173.87,304.6 174,304.47 174,304.44 174.12,304.32 174.63,304.32 174.76,304.44 174.76,304.47 174.89,304.6 175.39,304.6 175.52,304.47 175.52,304.44 175.65,304.32 176.15,304.32 176.28,304.44 P_CAL_CPU_OCP_0_N.1
PE_CAL_CPU_OCP_0_DP: length 66.5
  TOP w0.127: P_CAL_CPU_OCP_0_P.1 176.28,303.89 176.15,304.01 172.26,304.01 R184.2 171.4,304.01 170.99,304.01 C127.2 170.13,304.01 169.72,304.01 C128.2 168.86,304.01 166.07,304.01 164.81,303.79 162.31,304.23 159.81,303.79 157.31,304.23 154.81,303.79 152.3,304.23 152.3,304.23 152.29,304.23 152.28,304.23 148.14,304.23 129.06,323.31 129.06,326.69 128.91,326.84 P_OCPEDGE.B18
PE_CPU_OCP_0_DN: length 66.6
  TOP w0.127: P_OCP.B17 94.86,85.65 95.01,85.51 95.01,84.65 89.59,79.22 89.46,79.22 89.27,79.03 89.27,78.9 88.99,78.63 88.76,78.63 88.61,78.47 88.61,78.24 88.34,77.98 87.63,77.98 87.45,78.16 87.05,78.16 86.87,77.98 86.51,77.98 86.31,78.18 86.01,78.18 85.81,77.98 85.46,77.98 84.83,78.61 84.15,78.61 83.67,78.14 83.67,77.64 83.38,77.34 82.95,77.34 82.66,77.64 82.66,78.14 82.18,78.61 81.5,78.61 81.03,78.14 81.03,77.64 80.73,77.34 80.31,77.34 80.01,77.64 80.01,78.14 79.53,78.61 78.86,78.61 78.38,78.14 78.38,77.64 78.08,77.34 77.66,77.34 77.36,77.64 77.36,78.14 76.89,78.61 76.21,78.61 75.73,78.14 75.73,77.64 75.44,77.34 75.01,77.34 74.72,77.64 74.72,78.14 74.24,78.61 73.56,78.61 73.09,78.14 73.09,77.64 72.79,77.34 72.37,77.34 72.07,77.64 72.07,78.14 71.59,78.61 70.92,78.61 70.44,78.14 70.44,77.64 70.14,77.34 69.72,77.34 69.42,77.64 69.42,78.11 69.07,78.46 68.18,78.46 67.79,78.08 67.79,77.39 67.5,77.09 67.07,77.09 66.78,77.39 66.78,77.67 65.81,78.64 64.29,78.64 60.1,74.45 59.5,74.45 59.2,74.39 57.64,74.67 55.14,74.23 53.89,74.45 52.7,74.45 52.58,74.57
  TOP w0.152: P_CPU_OCP_0_N1.1 52.58,74.57
PE_CPU_OCP_0_DP: length 66.6
  TOP w0.127: 52.58,74.02 52.7,74.14 53.86,74.14 55.14,73.92 57.64,74.36 59.2,74.08 59.53,74.14 60.22,74.14 64.41,78.33 65.68,78.33 66.47,77.55 66.47,77.26 66.95,76.78 67.62,76.78 68.1,77.26 68.1,77.95 68.31,78.16 68.95,78.16 69.12,77.98 69.12,77.52 69.59,77.04 70.27,77.04 70.75,77.52 70.75,78.01 71.04,78.31 71.47,78.31 71.76,78.01 71.76,77.52 72.24,77.04 72.92,77.04 73.39,77.52 73.39,78.01 73.69,78.31 74.11,78.31 74.41,78.01 74.41,77.52 74.89,77.04 75.56,77.04 76.04,77.52 76.04,78.01 76.34,78.31 76.76,78.31 77.06,78.01 77.06,77.52 77.53,77.04 78.21,77.04 78.69,77.52 78.69,78.01 78.98,78.31 79.41,78.31 79.7,78.01 79.7,77.52 80.18,77.04 80.86,77.04 81.33,77.52 81.33,78.01 81.63,78.31 82.05,78.31 82.35,78.01 82.35,77.52 82.83,77.04 83.5,77.04 83.98,77.52 83.98,78.01 84.28,78.31 84.7,78.31 85.33,77.67 88.47,77.67 95.31,84.52 95.31,85.51 95.46,85.65 P_OCP.B18
  TOP w0.152: P_CPU_OCP_0_P1.1 52.58,74.02
PE_CPU_OCP_1_DN: length 66.6
  TOP w0.127: 69.44,68.58 69.57,68.71 69.57,73.68 70.36,74.47 71.88,74.47 72.18,74.77 72.18,75.34 72.66,75.82 73.33,75.82 73.81,75.34 73.81,73.42 74.11,73.13 74.53,73.13 74.83,73.42 74.83,75.34 75.31,75.82 75.98,75.82 76.46,75.34 76.46,73.42 76.76,73.13 77.18,73.13 77.48,73.42 77.48,75.34 77.95,75.82 78.63,75.82 79.1,75.34 79.1,73.42 79.4,73.13 79.82,73.13 80.12,73.42 80.12,75.34 80.6,75.82 81.27,75.82 81.75,75.34 81.75,73.42 82.05,73.13 82.47,73.13 82.77,73.42 82.77,75.34 83.25,75.82 83.92,75.82 84.4,75.34 84.4,73.42 84.7,73.13 85.12,73.13 85.42,73.42 85.42,74 85.89,74.47 87.38,74.47 96.81,83.91 96.81,85.51 96.66,85.65 P_OCP.B20
  TOP w0.152: P_CPU_OCP_1_N1.1 69.44,68.58
PE_CPU_OCP_1_DP: length 66.6
  TOP w0.127: P_OCP.B21 97.26,85.65 97.11,85.51 97.11,83.78 87.5,74.17 86.02,74.17 85.72,73.87 85.72,73.3 85.24,72.82 84.57,72.82 84.09,73.3 84.09,75.22 83.79,75.51 83.37,75.51 83.07,75.22 83.07,73.3 82.6,72.82 81.92,72.82 81.45,73.3 81.45,75.22 81.15,75.51 80.73,75.51 80.43,75.22 80.43,73.3 79.95,72.82 79.28,72.82 78.8,73.3 78.8,75.22 78.5,75.51 78.08,75.51 77.78,75.22 77.78,73.3 77.3,72.82 76.63,72.82 76.15,73.3 76.15,75.22 75.85,75.51 75.43,75.51 75.13,75.22 75.13,73.3 74.66,72.82 73.98,72.82 73.51,73.3 73.51,75.22 73.21,75.51 72.79,75.51 72.49,75.22 72.49,74.64 72.01,74.17 70.48,74.17 69.88,73.56 69.88,68.71 70,68.58
  TOP w0.152: P_CPU_OCP_1_P1.1 70,68.58
PE_CPU_OCP_2_DN: length 66.6
  TOP w0.127: 64.01,51.71 64.14,51.59 67.97,51.59 68.38,51.99 68.38,52.17 68.5,52.3 68.68,52.3 68.94,52.55 68.94,52.73 69.06,52.86 69.24,52.86 69.52,53.14 69.52,54.54 69.09,54.98 69.09,55.65 69.56,56.13 70.21,56.13 70.51,56.43 70.51,56.85 70.21,57.15 69.56,57.15 69.09,57.62 69.09,58.3 69.56,58.77 70.21,58.77 70.36,58.92 70.36,59.65 70.21,59.79 69.56,59.79 69.09,60.27 69.09,61.01 69.8,61.72 69.8,62.86 70.36,63.42 70.66,63.42 70.84,63.6 71.04,63.6 71.22,63.42 71.4,63.42 71.55,63.58 71.75,63.58 71.91,63.42 72.27,63.42 73.52,63.2 76.03,63.64 77.63,63.36 77.98,63.42 78.66,63.42 98.61,83.37 98.61,85.51 98.46,85.65 P_OCP.B23
  TOP w0.152: P_CPU_OCP_2_N1.1 64.01,51.71
PE_CPU_OCP_2_DP: length 66.6
  TOP w0.127: P_OCP.B24 99.06,85.65 98.91,85.51 98.91,83.24 78.79,63.12 78,63.12 77.63,63.05 76.03,63.33 73.52,62.89 72.25,63.12 70.48,63.12 70.1,62.74 70.1,61.59 69.39,60.88 69.39,60.4 69.69,60.1 70.34,60.1 70.66,59.77 70.66,58.79 70.34,58.47 69.69,58.47 69.39,58.17 69.39,57.75 69.69,57.45 70.34,57.45 70.82,56.97 70.82,56.3 70.34,55.82 69.69,55.82 69.39,55.52 69.39,55.1 69.82,54.67 69.82,53.01 68.1,51.28 64.14,51.28 64.01,51.16
  TOP w0.152: P_CPU_OCP_2_P1.1 64.01,51.16
PE_CPU_OCP_3_DN: length 66.7
  TOP w0.127: P_OCP.B26 100.26,85.65 100.41,85.51 100.41,83.06 89.34,71.99 89.34,69.77 89.21,69.65 87.02,69.65 86.51,69.14 86.51,68.16 86.99,67.69 89.28,67.69 89.41,67.56 89.41,65.79 89.28,65.66 88.85,65.66 87.7,65.86 85.3,65.44 84.05,65.66 83.31,65.66 83.01,65.35 83.01,63.46 83.31,63.16 83.91,63.16 85.19,62.93 87.69,63.37 89.2,63.11 89.48,63.16 89.74,63.16 89.87,63.03 89.87,62.31 89.46,61.9 88.95,61.9 88.4,61.8 86.59,62.12 84.09,61.68 83.37,61.81 83.02,61.81 82.42,62.41 81.58,62.41 80.72,61.54 80.72,60.76 81,60.48 81,57.28 80.87,57.15
  TOP w0.152: P_CPU_OCP_3_N1.1 80.87,57.15
PE_CPU_OCP_3_DP: length 66.7
  TOP w0.127: 81.43,57.15 81.31,57.28 81.31,60.6 81.03,60.88 81.03,61.42 81.71,62.1 82.3,62.1 82.9,61.5 83.34,61.5 84.09,61.37 86.59,61.81 88.4,61.49 88.98,61.59 89.59,61.59 90.17,62.18 90.17,63.16 89.86,63.46 89.46,63.46 89.2,63.42 87.69,63.68 85.19,63.24 83.94,63.46 83.44,63.46 83.31,63.59 83.31,65.23 83.44,65.35 84.02,65.35 85.3,65.13 87.7,65.55 88.82,65.35 89.41,65.35 89.71,65.66 89.71,67.69 89.41,68 87.11,68 86.82,68.29 86.82,69.01 87.15,69.34 89.34,69.34 89.64,69.65 89.64,71.86 100.71,82.93 100.71,85.51 100.86,85.65 P_OCP.B27
  TOP w0.152: P_CPU_OCP_3_P1.1 81.43,57.15
PE_CPU_OCP_4_DN: length 66.5
  TOP w0.127: 80.87,45.72 81,45.85 81,49.97 82.59,51.56 85.47,51.56 86.74,50.29 87.07,50.29 88.34,51.56 90.37,51.56 91.19,52.37 91.19,52.71 91.41,53.96 90.97,56.46 91.41,58.96 90.97,61.46 91.41,63.97 90.97,66.47 91.41,68.97 91.1,70.73 91.19,71.25 91.19,71.78 97.87,78.47 99.3,78.47 100.56,78.69 102.82,78.29 103.83,78.47 104.32,78.47 105.56,79.7 105.56,79.96 105.64,80.42 105.34,82.17 105.56,83.44 105.56,84.56 106.22,85.22 106.22,85.51 106.07,85.65 P_OCP.B30
  TOP w0.152: P_CPU_OCP_4_N.1 80.87,45.72
PE_CPU_OCP_4_DP: length 66.5
  TOP w0.127: P_OCP.B31 106.67,85.65 106.52,85.51 106.52,85.09 105.87,84.43 105.87,83.42 105.65,82.17 105.95,80.42 105.87,79.93 105.87,79.58 104.45,78.16 103.85,78.16 102.82,77.98 100.56,78.38 99.33,78.16 98,78.16 91.49,71.65 91.49,71.22 91.41,70.73 91.72,68.97 91.27,66.47 91.72,63.97 91.27,61.46 91.72,58.96 91.27,56.46 91.72,53.96 91.49,52.68 91.49,52.25 90.5,51.26 88.47,51.26 87.2,49.99 86.61,49.99 85.34,51.26 82.72,51.26 81.31,49.84 81.31,45.85 81.43,45.72
  TOP w0.152: P_CPU_OCP_4_P.1 81.43,45.72
PE_CPU_OCP_5_DN: length 66.5
  TOP w0.127: P_OCP.B33 107.87,85.65 108.02,85.51 108.02,84.43 107.29,83.7 107.29,83.35 107.06,82.07 107.39,80.21 107.29,79.63 107.29,79.1 105.14,76.94 104.05,76.94 102.84,76.73 100.38,77.16 99.13,76.94 98.61,76.94 93.6,71.93 93.6,71.25 93.51,70.71 93.82,68.93 93.38,66.43 93.82,63.93 93.38,61.42 93.82,58.92 93.38,56.42 93.82,53.92 93.6,52.67 93.6,51.89 94.23,51.26 96.65,51.26 97.74,50.16 99.24,50.16 100.33,51.26 102.54,51.26 103.86,49.94 103.86,45.85 103.73,45.72
  TOP w0.152: P_CPU_OCP_5_N.1 103.73,45.72
PE_CPU_OCP_5_DP: length 66.5
  TOP w0.127: 104.29,45.72 104.17,45.85 104.17,50.06 102.67,51.56 100.2,51.56 99.11,50.47 97.87,50.47 96.77,51.56 94.36,51.56 93.9,52.02 93.9,52.64 94.13,53.92 93.69,56.42 94.13,58.92 93.69,61.42 94.13,63.93 93.69,66.43 94.13,68.93 93.82,70.71 93.9,71.22 93.9,71.81 98.73,76.64 99.16,76.64 100.38,76.85 102.84,76.42 104.08,76.64 105.26,76.64 107.59,78.97 107.59,79.6 107.7,80.21 107.37,82.07 107.59,83.32 107.59,83.57 108.32,84.3 108.32,85.51 108.47,85.65 P_OCP.B34
  TOP w0.152: P_CPU_OCP_5_P.1 104.29,45.72
PE_CPU_OCP_6_DN: length 66.6
  TOP w0.127: 103.73,68.58 103.86,68.71 103.86,72.16 103.12,72.9 99.7,72.9 99.36,73.23 99.36,74.5 99.67,74.8 101.5,74.8 101.61,74.78 103,75.03 104.28,74.8 104.77,74.8 106.27,73.3 112.26,73.3 112.45,73.5 112.45,74.45 112.32,74.58 110.28,74.58 110.07,74.37 109.3,74.37 109.09,74.58 106.78,74.58 106.3,75.06 106.3,76.02 106.98,76.71 109.08,76.71 109.38,76.41 109.97,76.41 110.27,76.71 110.91,76.71 112.05,76.91 112.65,76.8 112.81,76.87 112.91,77.02 112.91,77.68 112.8,77.82 111.66,78.02 110.41,77.8 109.42,77.8 109.12,78.11 109.12,79.37 109.42,79.68 110.26,79.68 111.28,79.86 112.29,79.68 112.5,79.68 112.62,79.81 112.62,80.59 112.5,80.72 112.34,80.72 111.27,80.91 110.19,80.72 109.47,80.72 108.94,81.25 108.94,82.02 109.4,82.47 110.57,82.47 110.69,82.6 110.69,83.31 110.36,83.64 110.13,83.64 109.82,83.95 109.82,85.51 109.67,85.65 P_OCP.B36
  TOP w0.152: P_CPU_OCP_6_N.1 103.73,68.58
PE_CPU_OCP_6_DP: length 66.6
  TOP w0.127: P_OCP.B37 110.27,85.65 110.12,85.51 110.12,84.07 110.25,83.95 110.49,83.95 111,83.44 111,82.47 110.69,82.17 109.52,82.17 109.25,81.89 109.25,81.38 109.6,81.03 110.16,81.03 111.27,81.22 112.37,81.03 112.62,81.03 112.93,80.72 112.93,79.68 112.62,79.38 112.27,79.38 111.28,79.55 110.28,79.38 109.55,79.38 109.42,79.25 109.42,78.23 109.55,78.11 110.38,78.11 111.66,78.33 112.96,78.1 113.22,77.79 113.22,76.93 113.02,76.63 112.69,76.48 112.05,76.6 110.94,76.4 110.4,76.4 110.1,76.1 109.25,76.1 108.95,76.4 107.11,76.4 106.6,75.9 106.6,75.18 106.9,74.88 109.22,74.88 109.43,74.68 109.94,74.68 110.15,74.88 112.45,74.88 112.76,74.58 112.76,73.37 112.39,73 106.15,73 104.65,74.5 104.25,74.5 103,74.72 101.61,74.47 101.47,74.5 99.8,74.5 99.67,74.37 99.67,73.36 99.82,73.2 103.25,73.2 104.17,72.29 104.17,68.71 104.29,68.58
  TOP w0.152: P_CPU_OCP_6_P.1 104.29,68.58
PE_CPU_OCP_7_DN: length 66.5
  TOP w0.127: P_OCP.B39 111.47,85.65 111.62,85.51 111.62,84.62 112.49,83.76 114.17,83.76 114.3,83.63 114.3,83.14 114.52,81.89 114.08,79.38 114.52,76.88 114.08,74.38 114.52,71.88 114.08,69.38 114.52,66.88 114.1,64.5 114.3,63.37 114.3,62.48 113.87,62.05 113.28,62.05 113.16,62.18 113.16,63.55 112.85,63.86 111.43,63.86 111.12,63.55 111.12,62.11 111,61.99 109.81,61.99 109.68,62.11 109.68,63.66 109.33,64.01 107.85,64.01 107.54,63.7 107.54,62.11 107.42,61.99 106.15,61.99 106.02,62.11 106.02,63.53 105.54,64.01 105.03,64.01 103.96,64.19 101.64,63.79 100.39,64.01 99.44,64.01 99.14,63.7 99.14,62.28 99.44,61.98 100.13,61.98 101.4,61.75 102.68,61.98 103.12,61.98 103.86,61.24 103.86,57.28 103.73,57.15
  TOP w0.152: P_CPU_OCP_7_N.1 103.73,57.15
PE_CPU_OCP_7_DP: length 66.5
  TOP w0.127: 104.29,57.15 104.17,57.28 104.17,61.37 103.25,62.28 102.65,62.28 101.4,62.06 100.15,62.28 99.57,62.28 99.44,62.41 99.44,63.58 99.57,63.7 100.37,63.7 101.64,63.48 103.96,63.88 105,63.7 105.42,63.7 105.71,63.4 105.71,61.99 106.02,61.68 107.54,61.68 107.85,61.99 107.85,63.58 107.98,63.7 109.2,63.7 109.38,63.53 109.38,61.99 109.68,61.68 111.12,61.68 111.43,61.99 111.43,63.42 111.56,63.55 112.73,63.55 112.85,63.42 112.85,62.05 113.16,61.74 113.99,61.74 114.6,62.36 114.6,63.4 114.41,64.5 114.83,66.88 114.39,69.38 114.83,71.88 114.39,74.38 114.83,76.88 114.39,79.38 114.83,81.89 114.6,83.16 114.6,83.75 114.3,84.06 112.61,84.06 111.92,84.75 111.92,85.51 112.07,85.65 P_OCP.B40
  TOP w0.152: P_CPU_OCP_7_P.1 104.29,57.15
PE_CPU_OCP_8_DN: length 66.7
  TOP w0.127: 126.59,57.15 126.72,57.28 126.72,61.87 127.2,62.36 129.69,62.36 130.18,62.84 130.18,63.35 129.77,63.75 129.52,63.75 128.86,63.64 126.95,63.97 125.7,63.75 125.36,63.75 125.23,63.63 125.23,61.85 124.92,61.54 123.53,61.54 123.22,61.85 123.22,63.84 123.09,63.97 121.95,63.97 121.82,63.84 121.82,61.85 121.51,61.54 119.99,61.54 119.68,61.85 119.68,63.87 119.56,64 118.41,64 118.28,63.87 118.28,62.1 117.71,61.53 116.59,61.53 116.28,61.83 116.28,63.28 116.06,64.56 116.5,67.06 116.06,69.56 116.5,72.06 116.06,74.56 116.5,77.06 116.03,79.72 116.26,81.05 115.93,82.95 116.15,84.19 116.87,84.91 118.77,84.91 118.93,85.07 118.93,85.51 118.78,85.65 P_OCP.B44
  TOP w0.152: P_CPU_OCP_8_N.1 126.59,57.15
PE_CPU_OCP_8_DP: length 66.7
  TOP w0.127: 127.15,57.15 127.03,57.28 127.03,61.75 127.33,62.05 129.82,62.05 130.48,62.72 130.48,63.48 129.9,64.06 129.49,64.06 128.86,63.95 126.95,64.28 125.67,64.06 125.23,64.06 124.92,63.75 124.92,61.98 124.8,61.85 123.65,61.85 123.52,61.98 123.52,63.97 123.22,64.27 121.82,64.27 121.52,63.97 121.52,61.98 121.39,61.85 120.12,61.85 119.99,61.98 119.99,64 119.68,64.31 118.29,64.31 117.98,64 117.98,62.22 117.59,61.83 116.71,61.83 116.59,61.96 116.59,63.31 116.37,64.56 116.81,67.06 116.37,69.56 116.81,72.06 116.37,74.56 116.81,77.06 116.34,79.72 116.57,81.05 116.24,82.95 116.43,84.04 116.99,84.61 118.9,84.61 119.23,84.94 119.23,85.51 119.38,85.65 P_OCP.B45
  TOP w0.152: P_CPU_OCP_8_P.1 127.15,57.15
PE_CPU_OCP_9_DN: length 66.6
  TOP w0.127: P_OCP.B47 120.58,85.65 120.73,85.51 120.73,84.43 119.71,83.41 117.88,83.41 117.48,83.01 117.48,82.42 118.14,81.76 119.85,81.76 120.71,81.91 121.06,81.91 121.18,81.79 121.18,81.2 120.86,80.88 119.95,80.72 118.03,80.72 117.73,80.42 117.73,79.71 118.38,79.06 119.95,79.06 121.02,79.25 121.54,79.25 121.67,79.12 121.67,78.41 121.54,78.28 119.95,78 118.29,78 117.98,77.7 117.98,76.71 118.37,76.33 119.63,76.33 119.99,75.97 121.49,75.97 121.92,76.4 123.95,76.4 124.22,76.14 124.22,75.21 124.06,75.04 122.06,75.04 121.9,74.88 119.56,74.88 119.39,75.04 118.31,75.04 118.01,74.74 118.01,73.33 118.31,73.02 118.67,73.02 119.92,73.25 122.42,72.8 123.88,73.06 124.08,73.02 124.71,73.02 126.19,74.5 128.95,74.5 129.21,74.24 129.21,73.6 128.94,73.33 127.03,73.33 126.72,73.02 126.72,68.71 126.59,68.58
  TOP w0.152: P_CPU_OCP_9_N.1 126.59,68.58
PE_CPU_OCP_9_DP: length 66.6
  TOP w0.127: P_OCP.B48 121.18,85.65 121.03,85.51 121.03,84.31 119.84,83.11 118.01,83.11 117.79,82.89 117.79,82.54 118.26,82.07 119.82,82.07 120.68,82.22 121.18,82.22 121.49,81.91 121.49,81.08 121.01,80.6 119.97,80.42 118.16,80.42 118.03,80.29 118.03,79.83 118.5,79.36 119.92,79.36 120.99,79.55 121.67,79.55 121.97,79.25 121.97,78.28 121.69,78 119.98,77.7 118.41,77.7 118.29,77.57 118.29,76.84 118.49,76.63 119.76,76.63 120.11,76.28 121.36,76.28 121.79,76.71 124.08,76.71 124.53,76.26 124.53,75.08 124.18,74.74 122.19,74.74 122.02,74.57 119.43,74.57 119.27,74.74 118.44,74.74 118.31,74.61 118.31,73.46 118.44,73.33 118.65,73.33 119.92,73.56 122.42,73.11 123.88,73.37 124.11,73.33 124.59,73.33 126.06,74.8 129.08,74.8 129.51,74.37 129.51,73.47 129.07,73.02 127.15,73.02 127.03,72.9 127.03,68.71 127.15,68.58
  TOP w0.152: P_CPU_OCP_9_P.1 127.15,68.58
PE_CPU_OCP_10_DN: length 66.5
  TOP w0.127: 126.59,45.72 126.72,45.85 126.72,49.8 128.48,51.56 129.36,51.56 130.61,51.34 133.11,51.78 135.36,51.39 136.37,51.56 136.73,51.56 137.11,51.94 137.11,52.67 137.33,53.92 136.89,56.42 137.33,58.92 136.89,61.42 137.33,63.93 136.89,66.43 137.33,68.93 136.91,71.35 137.11,72.52 137.11,72.77 134.24,75.64 132.82,75.64 132.03,74.85 131.34,74.85 130.15,76.05 126.98,76.05 122.66,80.37 122.66,83.38 122.73,83.79 122.53,84.93 122.53,85.51 122.38,85.65 P_OCP.B50
  TOP w0.152: P_CPU_OCP_10_N.1 126.59,45.72
PE_CPU_OCP_10_DP: length 66.5
  TOP w0.127: 127.15,45.72 127.03,45.85 127.03,49.67 128.61,51.26 129.33,51.26 130.61,51.03 133.11,51.47 135.36,51.08 136.4,51.26 136.86,51.26 137.41,51.82 137.41,52.64 137.64,53.92 137.2,56.42 137.64,58.92 137.2,61.42 137.64,63.93 137.2,66.43 137.64,68.93 137.22,71.35 137.41,72.49 137.41,72.9 134.37,75.95 132.69,75.95 131.9,75.16 131.47,75.16 130.28,76.35 127.1,76.35 122.96,80.49 122.96,83.36 123.04,83.79 122.83,84.95 122.83,85.51 122.98,85.65 P_OCP.B51
  TOP w0.152: P_CPU_OCP_10_P.1 127.15,45.72
PE_CPU_OCP_11_DN: length 66.5
  TOP w0.127: 149.45,45.72 149.58,45.85 149.58,50.75 149.02,51.31 148.53,51.31 148.2,51.37 146.59,51.08 144.09,51.52 141.58,51.08 140.31,51.31 139.85,51.31 139.19,51.97 139.19,52.64 139.41,53.89 138.97,56.39 139.41,58.89 138.97,61.39 139.41,63.89 138.97,66.4 139.41,68.9 138.99,71.33 139.19,72.52 139.19,72.9 134.72,77.37 132.26,77.37 132.02,77.33 130.42,77.61 129.93,77.52 127.78,77.52 124.33,80.97 124.33,81.99 124.29,82.23 124.55,83.73 124.33,84.98 124.33,85.51 124.18,85.65 P_OCP.B53
  TOP w0.152: P_CPU_OCP_11_N.1 149.45,45.72
PE_CPU_OCP_11_DP: length 66.5
  TOP w0.127: P_OCP.B54 124.78,85.65 124.63,85.51 124.63,85 124.86,83.73 124.6,82.23 124.63,82.02 124.63,81.1 127.91,77.83 129.9,77.83 130.42,77.92 132.02,77.64 132.23,77.67 134.85,77.67 139.5,73.02 139.5,72.49 139.3,71.33 139.72,68.9 139.28,66.4 139.72,63.89 139.28,61.39 139.72,58.89 139.28,56.39 139.72,53.89 139.5,52.61 139.5,52.1 139.98,51.61 140.33,51.61 141.58,51.39 144.09,51.83 146.59,51.39 148.2,51.68 148.55,51.61 149.15,51.61 149.89,50.88 149.89,45.85 150.01,45.72
  TOP w0.152: P_CPU_OCP_11_P.1 150.01,45.72
PE_CPU_OCP_12_DN: length 66.6
  TOP w0.127: P_OCP.B56 125.98,85.65 126.13,85.51 126.13,84.9 126.35,83.65 126.13,82.39 126.13,81.79 128.93,78.99 129.86,78.99 130.7,79.14 132.42,78.84 135.61,78.84 143.63,70.82 144.31,70.82 145.23,71.74 145.65,71.74 145.95,71.45 145.95,71.02 143.55,68.63 143.55,67.95 144.03,67.47 144.71,67.47 147.1,69.87 147.53,69.87 147.82,69.57 147.82,69.15 145.43,66.75 145.43,66.08 145.9,65.6 146.58,65.6 148.98,68 149.4,68 149.7,67.7 149.7,67.28 148.77,66.36 148.77,65.68 149.58,64.87 149.58,64.31 149.8,63.06 149.36,60.56 149.71,58.55 149.58,57.8 149.58,57.28 149.45,57.15
  TOP w0.152: P_CPU_OCP_12_N.1 149.45,57.15
PE_CPU_OCP_12_DP: length 66.6
  TOP w0.127: P_OCP.B57 126.58,85.65 126.43,85.51 126.43,84.92 126.66,83.65 126.43,82.37 126.43,81.92 129.05,79.3 129.83,79.3 130.7,79.45 132.45,79.15 135.74,79.15 143.76,71.12 144.18,71.12 145.11,72.05 145.78,72.05 146.26,71.57 146.26,70.9 143.86,68.5 143.86,68.08 144.16,67.78 144.58,67.78 146.98,70.18 147.65,70.18 148.13,69.7 148.13,69.03 145.73,66.63 145.73,66.21 146.03,65.91 146.45,65.91 148.85,68.31 149.52,68.31 150,67.83 150,67.16 149.08,66.23 149.08,65.81 149.89,65 149.89,64.34 150.11,63.06 149.67,60.56 150.02,58.55 149.89,57.77 149.89,57.28 150.01,57.15
  TOP w0.152: P_CPU_OCP_12_P.1 150.01,57.15
PE_CPU_OCP_13_DN: length 66.5
  TOP w0.127: P_OCP.B59 127.78,85.65 127.93,85.51 127.93,85.06 128.09,84.15 127.93,83.24 127.93,82.59 129.9,80.62 132.78,80.62 134.47,80.32 135.5,80.5 137.16,80.21 137.97,80.21 144.15,74.04 145.29,74.04 145.77,74.52 145.77,74.97 146.01,75.22 146.44,75.22 146.79,74.87 146.79,73.04 147.26,72.57 147.94,72.57 148.41,73.04 148.41,74.71 148.71,75.01 149.13,75.01 149.43,74.71 149.43,73.55 149.91,73.08 150.58,73.08 151.06,73.55 151.06,74.71 151.36,75.01 151.78,75.01 152.08,74.71 152.08,73.55 152.56,73.08 153.23,73.08 153.71,73.55 153.71,74.71 154.01,75.01 154.43,75.01 154.73,74.71 154.73,73.55 155.2,73.08 155.88,73.08 156.35,73.55 156.35,74.71 156.65,75.01 157.07,75.01 157.37,74.71 157.37,73.55 157.85,73.08 158.52,73.08 159,73.55 159,73.74 159.3,74.04 159.9,74.04 161.01,72.93 161.01,68.71 160.88,68.58
  TOP w0.152: P_CPU_OCP_13_N.1 160.88,68.58
PE_CPU_OCP_13_DP: length 66.5
  TOP w0.127: P_OCP.B60 128.38,85.65 128.23,85.51 128.23,85.08 128.4,84.15 128.23,83.21 128.23,82.71 130.02,80.92 132.81,80.92 134.47,80.63 135.5,80.81 137.19,80.52 138.1,80.52 144.27,74.35 145.16,74.35 145.46,74.64 145.46,75.1 145.89,75.52 146.56,75.52 147.09,75 147.09,73.17 147.39,72.87 147.81,72.87 148.11,73.17 148.11,74.83 148.59,75.31 149.26,75.31 149.74,74.83 149.74,73.68 150.04,73.38 150.46,73.38 150.76,73.68 150.76,74.83 151.23,75.31 151.91,75.31 152.38,74.83 152.38,73.68 152.68,73.38 153.1,73.38 153.4,73.68 153.4,74.83 153.88,75.31 154.55,75.31 155.03,74.83 155.03,73.68 155.33,73.38 155.75,73.38 156.05,73.68 156.05,74.83 156.53,75.31 157.2,75.31 157.68,74.83 157.68,73.68 157.98,73.38 158.4,73.38 158.7,73.68 158.7,73.87 159.17,74.35 160.03,74.35 161.32,73.06 161.32,68.71 161.44,68.58
  TOP w0.152: P_CPU_OCP_13_P.1 161.44,68.58
PE_CPU_OCP_14_DN: length 66.6
  TOP w0.127: 160.88,80.01 161.01,80.14 161.01,85.85 160.88,85.98 157.54,85.98 157.41,85.85 157.41,84.84 157.11,84.53 156.09,84.53 155.79,84.84 155.79,85.85 155.66,85.98 154.89,85.98 154.77,85.85 154.77,85.06 154.46,84.75 153.44,84.75 153.14,85.06 153.14,85.85 153.01,85.98 152.25,85.98 152.12,85.85 152.12,84.92 151.81,84.62 150.8,84.62 150.49,84.92 150.49,85.38 150.05,85.82 149.61,85.82 149.45,85.66 149.45,81.46 149.02,81.03 148.08,81.03 147.65,81.46 147.65,81.97 147.45,82.17 146.81,82.17 146.51,81.87 146.51,79.63 146.21,79.32 145.19,79.32 144.88,79.63 144.88,81.79 144.76,81.91 143.99,81.91 143.87,81.79 143.87,79.71 143.56,79.4 142.54,79.4 142.24,79.71 142.24,81.79 142.11,81.91 140.76,81.91 139.51,82.14 137.26,81.74 134.76,82.18 134.26,82.09 132.08,82.09 129.73,84.44 129.73,85.51 129.58,85.65 P_OCP.B62
  TOP w0.152: P_CPU_OCP_14_N.1 160.88,80.01
PE_CPU_OCP_14_DP: length 66.6
  TOP w0.127: P_OCP.B63 130.18,85.65 130.03,85.51 130.03,84.57 132.21,82.4 134.23,82.4 134.76,82.49 137.26,82.05 139.51,82.45 140.78,82.22 142.24,82.22 142.54,81.91 142.54,79.83 142.67,79.71 143.43,79.71 143.56,79.83 143.56,81.91 143.87,82.22 144.88,82.22 145.19,81.91 145.19,79.76 145.32,79.63 146.08,79.63 146.21,79.76 146.21,82 146.69,82.47 147.57,82.47 147.96,82.09 147.96,81.58 148.21,81.33 148.89,81.33 149.15,81.58 149.15,85.79 149.48,86.12 150.18,86.12 150.8,85.5 150.8,85.05 150.92,84.92 151.69,84.92 151.82,85.05 151.82,85.98 152.12,86.28 153.14,86.28 153.44,85.98 153.44,85.18 153.57,85.06 154.33,85.06 154.46,85.18 154.46,85.98 154.77,86.28 155.78,86.28 156.09,85.98 156.09,84.96 156.22,84.84 156.98,84.84 157.11,84.96 157.11,85.98 157.41,86.28 161.01,86.28 161.32,85.98 161.32,80.14 161.44,80.01
  TOP w0.152: P_CPU_OCP_14_P.1 161.44,80.01
PE_CPU_OCP_15_DN: length 66.5
  TOP w0.127: P_OCP.B65 131.38,85.65 131.53,85.51 131.53,84.75 132.46,83.82 134.09,83.82 134.94,83.67 137.01,84.04 139.51,83.59 142.01,84.04 143.49,83.77 143.75,83.82 144.07,83.82 148.08,87.83 148.54,87.83 149.82,87.61 152.32,88.05 154.82,87.61 157.33,88.05 159.83,87.61 162.33,88.05 164.83,87.61 167.33,88.05 169.83,87.61 171.27,87.86 171.42,87.83 171.58,87.83 172.16,87.25 172.16,86.88 172.38,85.63 171.94,83.13 172.28,81.18 172.16,80.48 172.16,78.05 173.14,77.06 178.18,77.06 178.31,76.94
  TOP w0.152: P_CPU_OCP_15_N.1 178.31,76.94
